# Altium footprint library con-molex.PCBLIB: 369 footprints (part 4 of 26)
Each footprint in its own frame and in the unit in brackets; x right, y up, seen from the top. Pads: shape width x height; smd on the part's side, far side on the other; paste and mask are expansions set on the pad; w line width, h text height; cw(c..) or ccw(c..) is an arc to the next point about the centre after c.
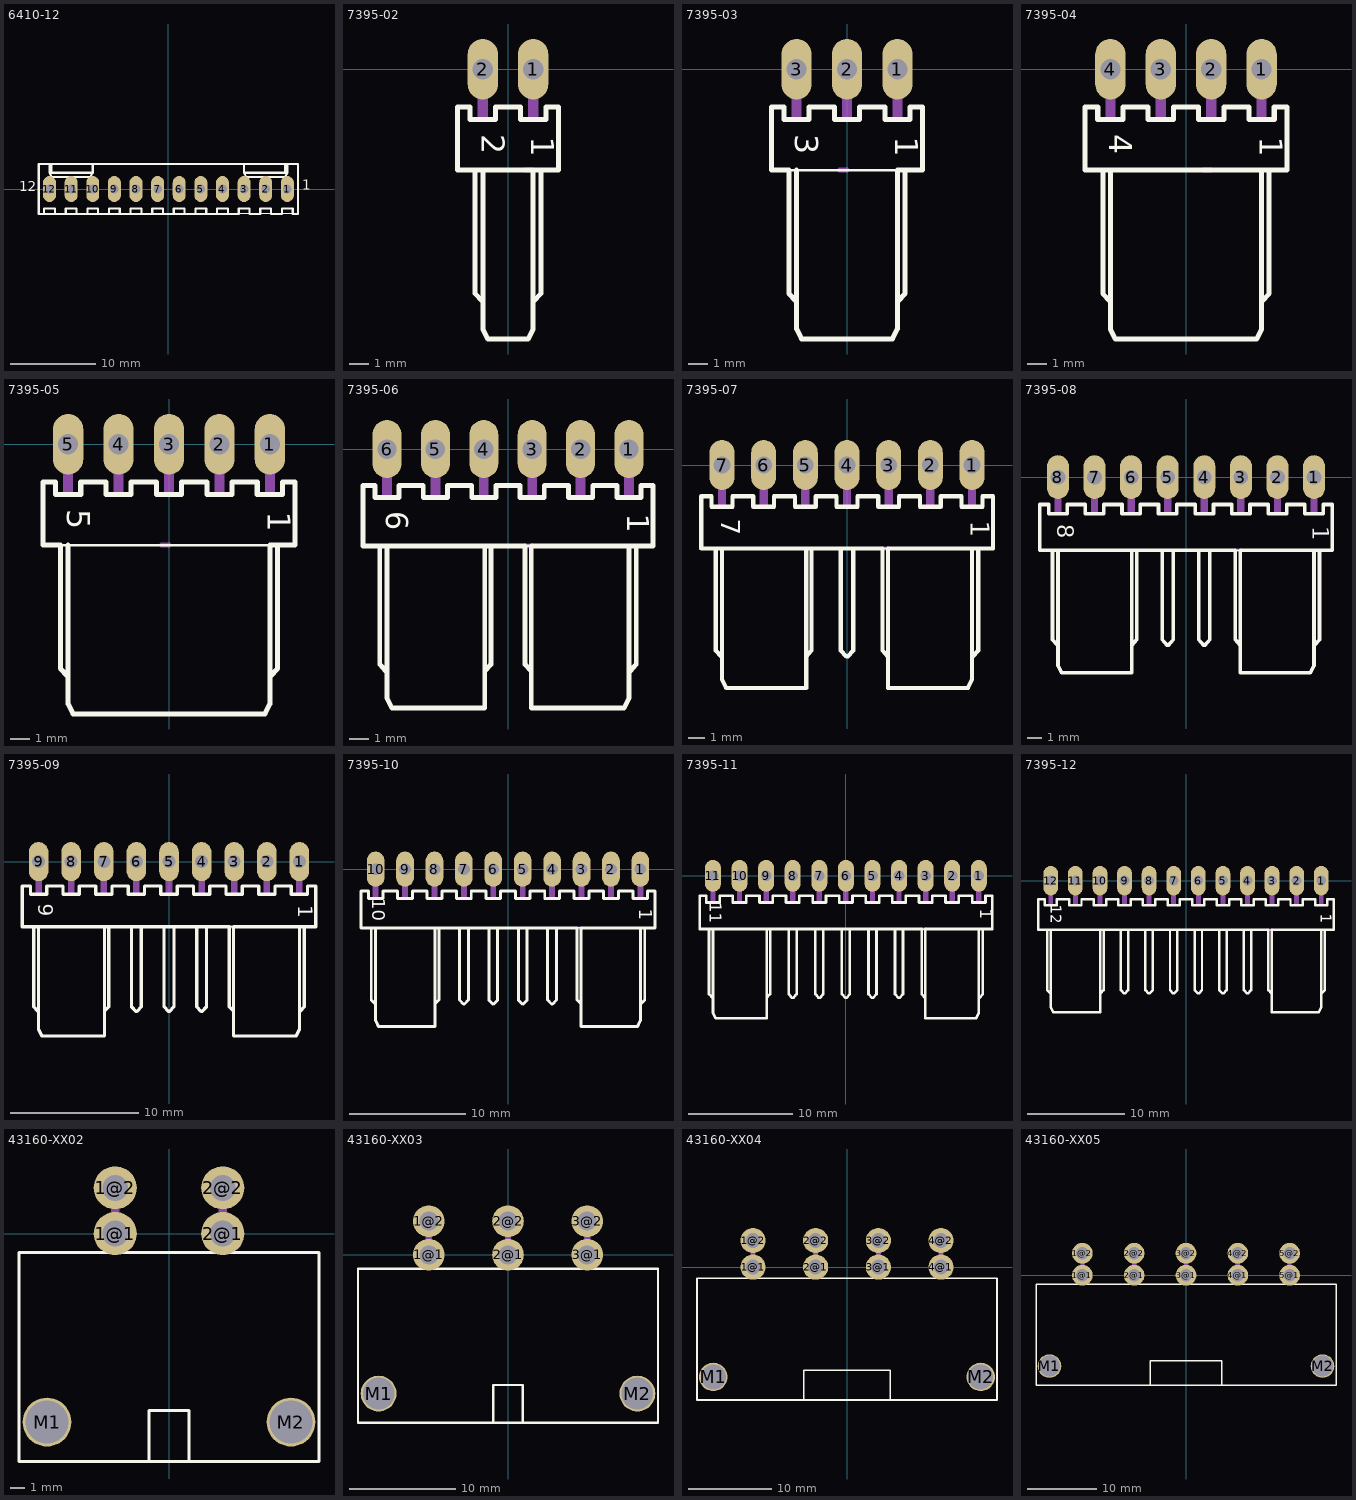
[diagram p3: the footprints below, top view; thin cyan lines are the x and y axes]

## 6410-12 [mil]
pads (12):
  oval 60x120 hole 40: 1(550,0) 2(450,0) 3(350,0) 4(250,0) 5(150,0) 6(50,0) 7(-50,0) 8(-150,0) 9(-250,0) 10(-350,0) 11(-450,0) 12(-550,0)
Top Overlay:
  lines w5: -550,100 -550,115 ; -305,-115 600,-115
  lines w10: -590,-115 -575,-115 -575,-90 -525,-90 -525,-115 -475,-115 -475,-90 -425,-90 -425,-115 -375,-115 -375,-90 -325,-90 -325,-115 325,-115 325,-90 375,-90 375,-115 425,-115 425,-90 475,-90 475,-115 525,-115 525,-90 575,-90 575,-115 600,-115 600,0 600,115 -300,115 -350,115 ; -305,-115 -600,-115 -600,0 -600,115 -550,115 ; -275,-115 -275,-90 -225,-90 -225,-115 ; -175,-115 -175,-90 -125,-90 -125,-115 ; -75,-115 -75,-90 -25,-90 -25,-115 ; 25,-115 25,-90 75,-90 75,-115 ; 125,-115 125,-90 175,-90 175,-115 ; 225,-115 225,-90 275,-90 275,-115 ; 350,115 350,75 ; 540,115 540,75 ; 550,115 550,75 ; -550,75 -550,115 ; -550,75 -540,75 ; -550,75 -540,55 -360,55 -350,75 ; -550,115 -540,115 ; -540,75 -350,75 ; -540,75 -540,115 ; -540,115 -350,115 ; -350,75 -350,115 ; 350,75 540,75 ; 350,75 360,55 540,55 550,75 ; 540,75 550,75
  text "1" at 618.94,-19.06 h77.5
  text "12" at -691.06,-27.06 h77.5
Mechanical 16:
  rectangle: -560,-10 -540,10
  rectangle: -460,-10 -440,10
  rectangle: -360,-10 -340,10
  rectangle: 340,-10 360,10
  rectangle: 440,-10 460,10
  rectangle: 540,-10 560,10
  rectangle: -260,-10 -240,10
  rectangle: 240,-10 260,10
  rectangle: 140,-10 160,10
  rectangle: -160,-10 -140,10
  rectangle: -60,-10 -40,10
  rectangle: 40,-10 60,10

## 7395-02 [mil]
pads (2):
  oval 60x120 hole 40: 1(50,0) 2(-50,0)
Top Overlay:
  lines w10: -52,-459 -65,-445 -65,-200 ; -50,-200 -50,-515 -40,-535 -2,-535 ; 2,-535 -2,-535 ; 52,-459 65,-445 65,-200 ; -65,-200 -100,-200 -100,-75 -75,-75 -75,-100 -25,-100 -25,-75 25,-75 25,-100 75,-100 75,-75 100,-75 100,-200 50,-200 ; -65,-200 50,-200 ; -2,-535 40,-535 50,-515 50,-200
  text "1" at 30.94,-133.94 h77.5
  text "2" at -67.06,-128.94 h77.5
Mechanical 16:
  rectangle: 40,-10 60,10
  rectangle: -60,-10 -40,10
  rectangle: 40,-99 60,-11
  rectangle: -60,-99 -40,-11
  lines w10: 35,-200 50,-200

## 7395-03 [mil]
pads (3):
  oval 60x120 hole 40: 1(100,0) 2(0,0) 3(-100,0)
Top Overlay:
  lines w5: -115,-200 100,-200
  lines w10: -102,-459 -115,-445 -115,-200 -150,-200 -150,-75 -125,-75 -125,-100 -75,-100 -75,-75 -25,-75 -25,-100 25,-100 25,-75 75,-75 75,-100 125,-100 125,-75 150,-75 150,-200 100,-200 100,-515 90,-535 -52,-535 ; -100,-200 -100,-515 -90,-535 -48,-535 ; 102,-459 115,-445 115,-200
  text "1" at 80.94,-133.94 h77.5
  text "3" at -117.06,-128.94 h77.5
Mechanical 16:
  rectangle: 90,-10 110,10
  rectangle: -10,-10 10,10
  rectangle: -110,-10 -90,10
  rectangle: 90,-99 110,-11
  rectangle: -10,-99 10,-11
  rectangle: -110,-99 -90,-11
  lines w10: -15,-200 0,-200

## 7395-04 [mil]
pads (4):
  oval 60x120 hole 40: 1(150,0) 2(50,0) 3(-50,0) 4(-150,0)
Top Overlay:
  lines w10: -152,-459 -165,-445 -165,-200 ; -150,-200 -150,-515 -140,-535 2,-535 ; -2,-535 140,-535 150,-515 150,-200 ; 152,-459 165,-445 165,-200 ; -165,-200 -200,-200 -200,-75 -175,-75 -175,-100 -125,-100 -125,-75 -75,-75 -75,-100 -25,-100 -25,-75 25,-75 25,-100 75,-100 75,-75 125,-75 125,-100 175,-100 175,-75 200,-75 200,-200 150,-200 ; -165,-200 150,-200
  text "1" at 130.94,-133.94 h77.5
  text "4" at -167.06,-128.94 h77.5
Mechanical 16:
  rectangle: 140,-10 160,10
  rectangle: 40,-10 60,10
  rectangle: -60,-10 -40,10
  rectangle: -160,-10 -140,10
  rectangle: 140,-99 160,-11
  rectangle: 40,-99 60,-11
  rectangle: -60,-99 -40,-11
  rectangle: -160,-99 -140,-11
  lines w10: 35,-200 50,-200

## 7395-05 [mil]
pads (5):
  oval 60x120 hole 40: 1(200,0) 2(100,0) 3(0,0) 4(-100,0) 5(-200,0)
Top Overlay:
  lines w5: -215,-200 200,-200
  lines w10: -202,-459 -215,-445 -215,-200 -250,-200 -250,-75 -225,-75 -225,-100 -175,-100 -175,-75 -125,-75 -125,-100 -75,-100 -75,-75 -25,-75 -25,-100 25,-100 25,-75 75,-75 75,-100 125,-100 125,-75 175,-75 175,-100 225,-100 225,-75 250,-75 250,-200 200,-200 200,-515 190,-535 -2,-535 ; -200,-200 -200,-515 -190,-535 2,-535 ; 202,-459 215,-445 215,-200
  text "1" at 180.94,-133.94 h77.5
  text "5" at -217.06,-128.94 h77.5
Mechanical 16:
  rectangle: 190,-10 210,10
  rectangle: 90,-10 110,10
  rectangle: -10,-10 10,10
  rectangle: -110,-10 -90,10
  rectangle: -210,-10 -190,10
  rectangle: 190,-99 210,-11
  rectangle: 90,-99 110,-11
  rectangle: -10,-99 10,-11
  rectangle: -110,-99 -90,-11
  rectangle: -210,-99 -190,-11
  lines w10: -15,-200 0,-200

## 7395-06 [mil]
pads (6):
  oval 60x120 hole 40: 1(250,0) 2(150,0) 3(50,0) 4(-50,0) 5(-150,0) 6(-250,0)
Top Overlay:
  lines w5: 35,-200 48,-200
  lines w10: -252,-459 -265,-445 -265,-200 ; -250,-200 -250,-515 -240,-535 -48,-535 -48,-200 ; -48,-459 -35,-445 -35,-200 ; 252,-459 265,-445 265,-200 ; -265,-200 -300,-200 -300,-75 -275,-75 -275,-100 -225,-100 -225,-75 -175,-75 -175,-100 -125,-100 -125,-75 -75,-75 -75,-100 -25,-100 -25,-75 25,-75 25,-100 75,-100 75,-75 125,-75 125,-100 175,-100 175,-75 225,-75 225,-100 275,-100 275,-75 300,-75 300,-200 250,-200 ; -265,-200 35,-200 35,-445 48,-459 ; 48,-459 48,-535 240,-535 250,-515 250,-200 ; 48,-459 48,-200 250,-200
  text "1" at 230.94,-133.94 h77.5
  text "6" at -267.06,-128.94 h77.5
Mechanical 16:
  rectangle: 240,-10 260,10
  rectangle: 140,-10 160,10
  rectangle: 40,-10 60,10
  rectangle: -60,-10 -40,10
  rectangle: -160,-10 -140,10
  rectangle: -260,-10 -240,10
  rectangle: 240,-99 260,-11
  rectangle: 140,-99 160,-11
  rectangle: 40,-99 60,-11
  rectangle: -60,-99 -40,-11
  rectangle: -160,-99 -140,-11
  rectangle: -260,-99 -240,-11
  lines w10: 35,-200 50,-200

## 7395-07 [mil]
pads (7):
  oval 60x120 hole 40: 1(300,0) 2(200,0) 3(100,0) 4(0,0) 5(-100,0) 6(-200,0) 7(-300,0)
Top Overlay:
  lines w5: 85,-200 98,-200
  lines w10: -302,-459 -315,-445 -315,-200 ; -300,-200 -300,-515 -290,-535 -98,-535 -98,-200 ; -98,-459 -85,-445 -85,-200 ; -2,-459 -15,-445 -15,-200 ; 2,-459 15,-445 15,-200 ; 302,-459 315,-445 315,-200 ; -315,-200 -350,-200 -350,-75 -325,-75 -325,-100 -275,-100 -275,-75 -225,-75 -225,-100 -175,-100 -175,-75 -125,-75 -125,-100 -75,-100 -75,-75 -25,-75 -25,-100 25,-100 25,-75 75,-75 75,-100 125,-100 125,-75 175,-75 175,-100 225,-100 225,-75 275,-75 275,-100 325,-100 325,-75 350,-75 350,-200 300,-200 ; -315,-200 -15,-200 ; -15,-200 85,-200 85,-445 98,-459 ; 98,-459 98,-535 290,-535 300,-515 300,-200 ; 98,-459 98,-200 300,-200
  text "1" at 280.94,-133.94 h77.5
  text "7" at -317.06,-128.94 h77.5
Mechanical 16:
  rectangle: 290,-10 310,10
  rectangle: 190,-10 210,10
  rectangle: 90,-10 110,10
  rectangle: -110,-10 -90,10
  rectangle: -210,-10 -190,10
  rectangle: -310,-10 -290,10
  rectangle: 290,-99 310,-11
  rectangle: 190,-99 210,-11
  rectangle: 90,-99 110,-11
  rectangle: -110,-99 -90,-11
  rectangle: -210,-99 -190,-11
  rectangle: -310,-99 -290,-11
  rectangle: -10,-99 10,-11
  rectangle: -10,-10 10,10
  lines w10: 85,-200 100,-200

## 7395-08 [mil]
pads (8):
  oval 60x120 hole 40: 1(350,0) 2(250,0) 3(150,0) 4(50,0) 5(-50,0) 6(-150,0) 7(-250,0) 8(-350,0)
Top Overlay:
  lines w5: 135,-200 148,-200
  lines w10: -352,-459 -365,-445 -365,-200 ; -350,-200 -350,-515 -340,-535 -148,-535 -148,-200 ; -148,-459 -135,-445 -135,-200 ; -52,-459 -65,-445 -65,-200 ; -48,-459 -35,-445 -35,-200 ; 48,-459 35,-445 35,-200 ; 52,-459 65,-445 65,-200 ; 352,-459 365,-445 365,-200 ; -365,-200 -400,-200 -400,-75 -375,-75 -375,-100 -325,-100 -325,-75 -275,-75 -275,-100 -225,-100 -225,-75 -175,-75 -175,-100 -125,-100 -125,-75 -75,-75 -75,-100 -25,-100 -25,-75 25,-75 25,-100 75,-100 75,-75 125,-75 125,-100 175,-100 175,-75 225,-75 225,-100 275,-100 275,-75 325,-75 325,-100 375,-100 375,-75 400,-75 400,-200 350,-200 ; -365,-200 -65,-200 ; -65,-200 35,-200 ; 35,-200 135,-200 135,-445 148,-459 ; 148,-459 148,-535 340,-535 350,-515 350,-200 ; 148,-459 148,-200 350,-200
  text "1" at 330.94,-133.94 h77.5
  text "8" at -367.06,-128.94 h77.5
Mechanical 16:
  rectangle: 340,-10 360,10
  rectangle: 240,-10 260,10
  rectangle: 140,-10 160,10
  rectangle: -160,-10 -140,10
  rectangle: -260,-10 -240,10
  rectangle: -360,-10 -340,10
  rectangle: 340,-99 360,-11
  rectangle: 240,-99 260,-11
  rectangle: 140,-99 160,-11
  rectangle: -160,-99 -140,-11
  rectangle: -260,-99 -240,-11
  rectangle: -360,-99 -340,-11
  rectangle: 40,-99 60,-11
  rectangle: 40,-10 60,10
  rectangle: -60,-99 -40,-11
  rectangle: -60,-10 -40,10
  lines w10: 135,-200 150,-200

## 7395-09 [mil]
pads (9):
  oval 60x120 hole 40: 1(400,0) 2(300,0) 3(200,0) 4(100,0) 5(0,0) 6(-100,0) 7(-200,0) 8(-300,0) 9(-400,0)
Top Overlay:
  lines w5: 185,-200 198,-200
  lines w10: -402,-459 -415,-445 -415,-200 ; -400,-200 -400,-515 -390,-535 -198,-535 -198,-200 ; -198,-459 -185,-445 -185,-200 ; -102,-459 -115,-445 -115,-200 ; -98,-459 -85,-445 -85,-200 ; -2,-459 -15,-445 -15,-200 ; 2,-459 15,-445 15,-200 ; 98,-459 85,-445 85,-200 ; 102,-459 115,-445 115,-200 ; 402,-459 415,-445 415,-200 ; -415,-200 -450,-200 -450,-75 -425,-75 -425,-100 -375,-100 -375,-75 -325,-75 -325,-100 -275,-100 -275,-75 -225,-75 -225,-100 -175,-100 -175,-75 -125,-75 -125,-100 -75,-100 -75,-75 -25,-75 -25,-100 25,-100 25,-75 75,-75 75,-100 125,-100 125,-75 175,-75 175,-100 225,-100 225,-75 275,-75 275,-100 325,-100 325,-75 375,-75 375,-100 425,-100 425,-75 450,-75 450,-200 400,-200 ; -415,-200 -115,-200 ; -115,-200 -15,-200 ; -15,-200 85,-200 ; 85,-200 185,-200 185,-445 198,-459 ; 198,-459 198,-535 390,-535 400,-515 400,-200 ; 198,-459 198,-200 400,-200
  text "1" at 380.94,-133.94 h77.5
  text "9" at -417.06,-128.94 h77.5
Mechanical 16:
  rectangle: 390,-10 410,10
  rectangle: 290,-10 310,10
  rectangle: 190,-10 210,10
  rectangle: -210,-10 -190,10
  rectangle: -310,-10 -290,10
  rectangle: -410,-10 -390,10
  rectangle: 390,-99 410,-11
  rectangle: 290,-99 310,-11
  rectangle: 190,-99 210,-11
  rectangle: -210,-99 -190,-11
  rectangle: -310,-99 -290,-11
  rectangle: -410,-99 -390,-11
  rectangle: 90,-99 110,-11
  rectangle: 90,-10 110,10
  rectangle: -10,-99 10,-11
  rectangle: -10,-10 10,10
  rectangle: -110,-99 -90,-11
  rectangle: -110,-10 -90,10
  lines w10: 185,-200 200,-200

## 7395-10 [mil]
pads (10):
  oval 60x120 hole 40: 1(450,0) 2(350,0) 3(250,0) 4(150,0) 5(50,0) 6(-50,0) 7(-150,0) 8(-250,0) 9(-350,0) 10(-450,0)
Top Overlay:
  lines w5: 235,-200 248,-200
  lines w10: -452,-459 -465,-445 -465,-200 ; -450,-200 -450,-515 -440,-535 -248,-535 -248,-200 ; -248,-459 -235,-445 -235,-200 ; -152,-459 -165,-445 -165,-200 ; -148,-459 -135,-445 -135,-200 ; -52,-459 -65,-445 -65,-200 ; -48,-459 -35,-445 -35,-200 ; 48,-459 35,-445 35,-200 ; 52,-459 65,-445 65,-200 ; 148,-459 135,-445 135,-200 ; 152,-459 165,-445 165,-200 ; 452,-459 465,-445 465,-200 ; -465,-200 -500,-200 -500,-75 -475,-75 -475,-100 -425,-100 -425,-75 -375,-75 -375,-100 -325,-100 -325,-75 -275,-75 -275,-100 -225,-100 -225,-75 -175,-75 -175,-100 -125,-100 -125,-75 -75,-75 -75,-100 -25,-100 -25,-75 25,-75 25,-100 75,-100 75,-75 125,-75 125,-100 175,-100 175,-75 225,-75 225,-100 275,-100 275,-75 325,-75 325,-100 375,-100 375,-75 425,-75 425,-100 475,-100 475,-75 500,-75 500,-200 450,-200 ; -465,-200 -165,-200 ; -165,-200 -65,-200 ; -65,-200 35,-200 ; 35,-200 135,-200 ; 135,-200 235,-200 235,-445 248,-459 ; 248,-459 248,-535 440,-535 450,-515 450,-200 ; 248,-459 248,-200 450,-200
  text "1" at 430.94,-133.94 h77.5
  text "10" at -477.06,-98.94 h77.5
Mechanical 16:
  rectangle: 440,-10 460,10
  rectangle: 340,-10 360,10
  rectangle: 240,-10 260,10
  rectangle: -260,-10 -240,10
  rectangle: -360,-10 -340,10
  rectangle: -460,-10 -440,10
  rectangle: 440,-99 460,-11
  rectangle: 340,-99 360,-11
  rectangle: 240,-99 260,-11
  rectangle: -260,-99 -240,-11
  rectangle: -360,-99 -340,-11
  rectangle: -460,-99 -440,-11
  rectangle: 140,-99 160,-11
  rectangle: 140,-10 160,10
  rectangle: 40,-99 60,-11
  rectangle: 40,-10 60,10
  rectangle: -160,-99 -140,-11
  rectangle: -160,-10 -140,10
  rectangle: -60,-99 -40,-11
  rectangle: -60,-10 -40,10
  lines w10: 235,-200 250,-200

## 7395-11 [mil]
pads (11):
  oval 60x120 hole 40: 1(500,0) 2(400,0) 3(300,0) 4(200,0) 5(100,0) 6(0,0) 7(-100,0) 8(-200,0) 9(-300,0) 10(-400,0) 11(-500,0)
Top Overlay:
  lines w5: 285,-200 298,-200
  lines w10: -502,-459 -515,-445 -515,-200 ; -500,-200 -500,-515 -490,-535 -298,-535 -298,-200 ; -298,-459 -285,-445 -285,-200 ; -202,-459 -215,-445 -215,-200 ; -198,-459 -185,-445 -185,-200 ; -102,-459 -115,-445 -115,-200 ; -98,-459 -85,-445 -85,-200 ; -2,-459 -15,-445 -15,-200 ; 2,-459 15,-445 15,-200 ; 98,-459 85,-445 85,-200 ; 102,-459 115,-445 115,-200 ; 198,-459 185,-445 185,-200 ; 202,-459 215,-445 215,-200 ; 502,-459 515,-445 515,-200 ; -515,-200 -550,-200 -550,-75 -525,-75 -525,-100 -475,-100 -475,-75 -425,-75 -425,-100 -375,-100 -375,-75 -325,-75 -325,-100 -275,-100 -275,-75 -225,-75 -225,-100 -175,-100 -175,-75 -125,-75 -125,-100 -75,-100 -75,-75 -25,-75 -25,-100 25,-100 25,-75 75,-75 75,-100 125,-100 125,-75 175,-75 175,-100 225,-100 225,-75 275,-75 275,-100 325,-100 325,-75 375,-75 375,-100 425,-100 425,-75 475,-75 475,-100 525,-100 525,-75 550,-75 550,-200 500,-200 ; -515,-200 -215,-200 ; -215,-200 -115,-200 ; -115,-200 -15,-200 ; -15,-200 85,-200 ; 85,-200 185,-200 ; 185,-200 285,-200 285,-445 298,-459 ; 298,-459 298,-535 490,-535 500,-515 500,-200 ; 298,-459 298,-200 500,-200
  text "1" at 490.94,-123.94 h77.5
  text "11" at -527.06,-98.94 h77.5
Mechanical 16:
  rectangle: 490,-10 510,10
  rectangle: 390,-10 410,10
  rectangle: 290,-10 310,10
  rectangle: -310,-10 -290,10
  rectangle: -410,-10 -390,10
  rectangle: -510,-10 -490,10
  rectangle: 490,-99 510,-11
  rectangle: 390,-99 410,-11
  rectangle: 290,-99 310,-11
  rectangle: -310,-99 -290,-11
  rectangle: -410,-99 -390,-11
  rectangle: -510,-99 -490,-11
  rectangle: 190,-99 210,-11
  rectangle: 190,-10 210,10
  rectangle: 90,-99 110,-11
  rectangle: 90,-10 110,10
  rectangle: -210,-99 -190,-11
  rectangle: -210,-10 -190,10
  rectangle: -10,-99 10,-11
  rectangle: -10,-10 10,10
  rectangle: -110,-99 -90,-11
  rectangle: -110,-10 -90,10
  lines w10: 285,-200 300,-200

## 7395-12 [mil]
pads (12):
  oval 60x120 hole 40: 1(550,0) 2(450,0) 3(350,0) 4(250,0) 5(150,0) 6(50,0) 7(-50,0) 8(-150,0) 9(-250,0) 10(-350,0) 11(-450,0) 12(-550,0)
Top Overlay:
  lines w5: 335,-200 348,-200
  lines w10: -552,-459 -565,-445 -565,-200 ; -550,-200 -550,-515 -540,-535 -348,-535 -348,-200 ; -348,-459 -335,-445 -335,-200 ; -252,-459 -265,-445 -265,-200 ; -248,-459 -235,-445 -235,-200 ; -152,-459 -165,-445 -165,-200 ; -148,-459 -135,-445 -135,-200 ; -52,-459 -65,-445 -65,-200 ; -48,-459 -35,-445 -35,-200 ; 48,-459 35,-445 35,-200 ; 52,-459 65,-445 65,-200 ; 148,-459 135,-445 135,-200 ; 152,-459 165,-445 165,-200 ; 248,-459 235,-445 235,-200 ; 252,-459 265,-445 265,-200 ; 552,-459 565,-445 565,-200 ; -565,-200 -600,-200 -600,-75 -575,-75 -575,-100 -525,-100 -525,-75 -475,-75 -475,-100 -425,-100 -425,-75 -375,-75 -375,-100 -325,-100 -325,-75 -275,-75 -275,-100 -225,-100 -225,-75 -175,-75 -175,-100 -125,-100 -125,-75 -75,-75 -75,-100 -25,-100 -25,-75 25,-75 25,-100 75,-100 75,-75 125,-75 125,-100 175,-100 175,-75 225,-75 225,-100 275,-100 275,-75 325,-75 325,-100 375,-100 375,-75 425,-75 425,-100 475,-100 475,-75 525,-75 525,-100 575,-100 575,-75 600,-75 600,-200 550,-200 ; -565,-200 -265,-200 ; -265,-200 -165,-200 ; -165,-200 -65,-200 ; -65,-200 35,-200 ; 35,-200 135,-200 ; 135,-200 235,-200 ; 235,-200 335,-200 335,-445 348,-459 ; 348,-459 348,-535 540,-535 550,-515 550,-200 ; 348,-459 348,-200 550,-200
  text "1" at 530.94,-133.94 h77.5
  text "12" at -567.06,-98.94 h77.5
Mechanical 16:
  rectangle: 540,-10 560,10
  rectangle: 440,-10 460,10
  rectangle: 340,-10 360,10
  rectangle: -360,-10 -340,10
  rectangle: -460,-10 -440,10
  rectangle: -560,-10 -540,10
  rectangle: 540,-99 560,-11
  rectangle: 440,-99 460,-11
  rectangle: 340,-99 360,-11
  rectangle: -360,-99 -340,-11
  rectangle: -460,-99 -440,-11
  rectangle: -560,-99 -540,-11
  rectangle: 240,-99 260,-11
  rectangle: 240,-10 260,10
  rectangle: 140,-99 160,-11
  rectangle: 140,-10 160,10
  rectangle: -260,-99 -240,-11
  rectangle: -260,-10 -240,10
  rectangle: 40,-99 60,-11
  rectangle: 40,-10 60,10
  rectangle: -60,-99 -40,-11
  rectangle: -60,-10 -40,10
  rectangle: -160,-99 -140,-11
  rectangle: -160,-10 -140,10
  lines w10: 335,-200 350,-200

## 43160-XX02 [mm]
pads (6):
  round 3 hole 1.8: 1@1(-3.745,0) 1@2(-3.745,3.18) 2@1(3.745,0) 2@2(3.745,3.18)
  round 3.4 hole 3: M1(-8.495,-13.13) M2(8.495,-13.13)
Top Overlay:
  lines w0.203: -1.4,-15.8 -1.4,-12.325 1.4,-12.325 1.4,-15.85 ; -10.445,-15.885 -10.445,-1.325 10.445,-1.325 10.445,-15.885 -10.445,-15.885
Mechanical 16:
  lines w0.6: -3.745,-1.1 -3.745,3.745 ; 3.745,-1.1 3.745,3.745

## 43160-XX03 [mm]
pads (8):
  round 3 hole 1.8: 1@1(-7.49,0) 1@2(-7.49,3.18) 2@1(0,0) 2@2(0,3.18) 3@1(7.49,0) 3@2(7.49,3.18)
  round 3.4 hole 3: M1(-12.24,-13.13) M2(12.24,-13.13)
Top Overlay:
  lines w0.203: -1.4,-15.8 -1.4,-12.325 1.4,-12.325 1.4,-15.85 ; -14.19,-15.885 -14.19,-1.325 14.19,-1.325 14.19,-15.885 -14.19,-15.885
Mechanical 16:
  lines w0.6: -7.49,-1.1 -7.49,3.745 ; 0,-1.1 0,3.745 ; 7.49,-1.1 7.49,3.745

## 43160-XX04 [mm]
pads (10):
  round 3 hole 1.8: 1@1(-11.235,0) 1@2(-11.235,3.18) 2@1(-3.745,0) 2@2(-3.745,3.18) 3@1(3.745,0) 3@2(3.745,3.18) 4@1(11.235,0) 4@2(11.235,3.18)
  round 3.4 hole 3: M1(-15.985,-13.13) M2(15.985,-13.13)
Top Overlay:
  lines w0.203: -5.175,-15.8 -5.175,-12.325 5.175,-12.325 5.175,-15.85 ; -17.935,-15.885 -17.935,-1.325 17.935,-1.325 17.935,-15.885 -17.935,-15.885
Mechanical 16:
  lines w0.6: -11.235,-1.1 -11.235,3.745 ; -3.745,-1.1 -3.745,3.745 ; 3.745,-1.1 3.745,3.745 ; 11.235,-1.1 11.235,3.745

## 43160-XX05 [mm]
pads (12):
  round 3 hole 1.8: 1@1(-14.98,0) 1@2(-14.98,3.18) 2@1(-7.49,0) 2@2(-7.49,3.18) 3@1(0,0) 3@2(0,3.18) 4@1(7.49,0) 4@2(7.49,3.18) 5@1(14.98,0) 5@2(14.98,3.18)
  round 3.4 hole 3: M1(-19.73,-13.13) M2(19.73,-13.13)
Top Overlay:
  lines w0.203: -5.175,-15.8 -5.175,-12.325 5.175,-12.325 5.175,-15.85 ; -21.68,-15.885 -21.68,-1.325 21.68,-1.325 21.68,-15.885 -21.68,-15.885
Mechanical 16:
  lines w0.6: -14.98,-1.1 -14.98,3.745 ; -7.49,-1.1 -7.49,3.745 ; 0,-1.1 0,3.745 ; 7.49,-1.1 7.49,3.745 ; 14.98,-1.1 14.98,3.745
